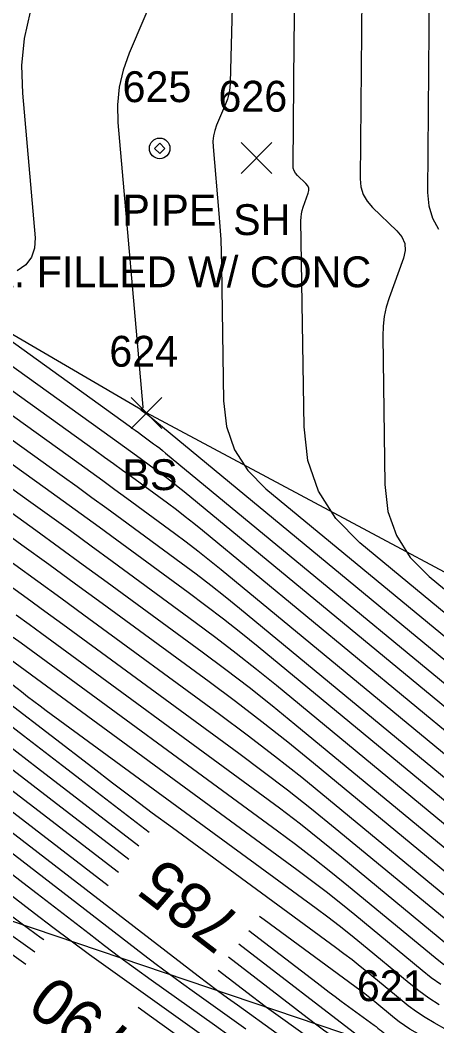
# Model space of a CAD drawing. Extents: x 1650836 to 1652450, y 332578 to 333908.
# Drawn here: x 1652265.5 to 1652292.5, y 332737.3 to 332802.5 of the extents above; entities that cross this region are included whole.
import ezdxf

# ---------------------------------------------------------------- set-up
doc = ezdxf.new("R2010")
doc.units = 0
for name, color, linetype in [('L_A', 7, 'Continuous'), ('L_I', 7, 'Continuous'), ('L_TIC', 7, 'Continuous'), ('LAWA', 7, 'Continuous'), ('LELB', 7, 'Continuous'), ('LSOGCMA', 7, 'Continuous'), ('LSOGCMA_T', 7, 'Continuous'), ('LSOGCMI', 7, 'Continuous'), ('M_A', 7, 'Continuous'), ('M_C', 7, 'Continuous'), ('M_I', 7, 'Continuous'), ('MPIP', 7, 'Continuous')]:
    doc.layers.add(name, color=color, linetype=linetype)

msp = doc.modelspace()

# ---------------------------------------------------------------- linework, layer by layer
at = {"layer": 'L_TIC'}
for points in [[(1652279.805, 332792.553), (1652281.805, 332794.553)], [(1652281.805, 332792.553), (1652279.805, 332794.553)], [(1652272.674, 332776.021), (1652274.674, 332778.021)], [(1652274.674, 332776.021), (1652272.674, 332778.021)]]:
    msp.add_lwpolyline(points, dxfattribs=at)
at = {"layer": 'LAWA'}
msp.add_lwpolyline([(1652408.76, 332665.713), (1652363.38, 332695.402), (1652324.46, 332714.991), (1652289.155, 332735.895), (1652253.497, 332747.946), (1652218.614, 332766.122), (1652198.198, 332775.017), (1652146.456, 332804.843), (1652136.841, 332807.592), (1652091.374, 332831.511), (1652057.601, 332848.138), (1652027.653, 332867.625)], dxfattribs=at)
at = {"layer": 'LELB'}
msp.add_lwpolyline([(1652415.318, 332676.268), (1652374.578, 332707.318), (1652335.114, 332741.334), (1652308.938, 332758.195), (1652273.674, 332777.021), (1652240.738, 332796.253), (1652212.676, 332810.498), (1652191.609, 332828.678)], dxfattribs=at)
at = {"layer": 'LSOGCMA'}
for points in [[(1652279.538, 332814.747), (1652279.104, 332798.44), (1652279.078, 332798.076), (1652279.017, 332797.72), (1652278.924, 332797.371), (1652278.797, 332797.029), (1652278.221, 332795.677), (1652278.099, 332795.336), (1652278.021, 332794.987), (1652277.987, 332794.632), (1652277.997, 332794.269), (1652278.375, 332789.946), (1652278.441, 332789.103), (1652278.492, 332788.26), (1652278.527, 332787.415), (1652278.547, 332786.57), (1652278.678, 332777.807), (1652278.868, 332776.144), (1652279.388, 332774.639), (1652280.238, 332773.293), (1652281.417, 332772.104), (1652304.103, 332753.383)], [(1652207.289, 332796.117), (1652228.455, 332780.692), (1652228.555, 332780.619), (1652228.655, 332780.547), (1652228.756, 332780.475), (1652228.857, 332780.404), (1652229.261, 332780.119), (1652229.361, 332780.048), (1652229.462, 332779.976), (1652229.561, 332779.902), (1652229.66, 332779.829), (1652231.418, 332778.505), (1652231.744, 332778.261), (1652232.072, 332778.017), (1652232.4, 332777.776), (1652232.73, 332777.535), (1652253.597, 332762.371), (1652257.064, 332759.833), (1652260.514, 332757.272), (1652263.946, 332754.687), (1652267.36, 332752.078), (1652272.52, 332748.107)], [(1652294.692, 332745.911), (1652284.503, 332754.319), (1652282.838, 332755.673), (1652281.154, 332757.003), (1652279.451, 332758.309), (1652277.729, 332759.59), (1652270.803, 332764.666), (1652269.071, 332765.934), (1652267.335, 332767.196), (1652265.596, 332768.455), (1652263.854, 332769.709), (1652256.417, 332775.051), (1652254.6, 332776.364), (1652252.791, 332777.687), (1652250.989, 332779.02), (1652249.194, 332780.363), (1652240.495, 332786.912), (1652238.442, 332788.444), (1652236.378, 332789.961), (1652234.301, 332791.461), (1652232.213, 332792.944), (1652229.96, 332794.531)], [(1652279.653, 332742.619), (1652287.635, 332736.477), (1652287.714, 332736.417), (1652287.794, 332736.357), (1652287.874, 332736.298), (1652287.955, 332736.24), (1652288.279, 332736.009), (1652288.359, 332735.951), (1652288.439, 332735.892), (1652288.518, 332735.831), (1652288.597, 332735.77), (1652289.157, 332735.326), (1652289.277, 332735.232), (1652289.396, 332735.137), (1652289.515, 332735.042), (1652289.634, 332734.946), (1652309.319, 332719.049)]]:
    msp.add_lwpolyline(points, dxfattribs=at)
at = {"layer": 'LSOGCMI'}
for points in [[(1652287.7, 332811.246), (1652287.539, 332792.197), (1652287.585, 332791.671), (1652287.731, 332791.187), (1652287.978, 332790.746), (1652288.325, 332790.347), (1652289.914, 332788.839), (1652290.238, 332788.444), (1652290.417, 332788.016), (1652290.449, 332787.552), (1652290.336, 332787.054), (1652289.408, 332784.485), (1652289.219, 332783.881), (1652289.087, 332783.267), (1652289.012, 332782.643), (1652288.993, 332782.01), (1652289.136, 332772.375), (1652289.335, 332770.639), (1652289.878, 332769.068), (1652290.765, 332767.663), (1652291.996, 332766.423), (1652305.777, 332755.05)], [(1652292.795, 332809.573), (1652292.229, 332808.51), (1652292.032, 332807.144), (1652291.899, 332791.32), (1652291.974, 332790.452), (1652292.215, 332789.656), (1652292.621, 332788.929)], [(1652298.244, 332747.551), (1652280.907, 332761.858), (1652279.794, 332762.763), (1652278.67, 332763.651), (1652277.532, 332764.523), (1652276.382, 332765.379), (1652271.757, 332768.77), (1652270.599, 332769.616), (1652269.44, 332770.459), (1652268.279, 332771.3), (1652267.115, 332772.138), (1652249.162, 332785.034), (1652248.082, 332785.814), (1652247.007, 332786.6), (1652245.936, 332787.392), (1652244.869, 332788.191), (1652240.612, 332791.396), (1652239.544, 332792.193), (1652238.471, 332792.981), (1652237.391, 332793.761), (1652236.305, 332794.533), (1652216.969, 332808.155)], [(1652274.384, 332804.669), (1652272.543, 332800.346), (1652272.153, 332799.254), (1652271.904, 332798.14), (1652271.795, 332797.003), (1652271.827, 332795.844), (1652273.44, 332777.39), (1652273.439, 332777.368), (1652273.433, 332777.349), (1652273.42, 332777.333), (1652273.403, 332777.32), (1652273.319, 332777.275), (1652273.304, 332777.264), (1652273.298, 332777.252), (1652273.302, 332777.239), (1652273.316, 332777.225), (1652273.638, 332776.994), (1652273.663, 332776.976), (1652273.689, 332776.957), (1652273.702, 332776.947), (1652273.714, 332776.937), (1652303.266, 332752.55)], [(1652304.94, 332754.217), (1652287.508, 332768.602), (1652285.952, 332770.171), (1652284.83, 332771.948), (1652284.143, 332773.935), (1652283.891, 332776.131), (1652283.693, 332789.481), (1652283.7, 332789.705), (1652283.726, 332789.925), (1652283.773, 332790.141), (1652283.839, 332790.354), (1652284.167, 332791.261), (1652284.207, 332791.436), (1652284.195, 332791.6), (1652284.132, 332791.751), (1652284.018, 332791.89), (1652283.457, 332792.422), (1652283.335, 332792.563), (1652283.248, 332792.718), (1652283.196, 332792.889), (1652283.18, 332793.075), (1652283.248, 332801.062), (1652283.263, 332802.458), (1652283.284, 332803.853)], [(1652226.364, 332803.026), (1652237.669, 332795.062), (1652238.421, 332794.528), (1652239.168, 332793.988), (1652239.912, 332793.442), (1652240.651, 332792.89), (1652243.598, 332790.671), (1652244.337, 332790.119), (1652245.078, 332789.57), (1652245.823, 332789.026), (1652246.57, 332788.486), (1652268.202, 332772.947), (1652269.173, 332772.248), (1652270.142, 332771.547), (1652271.109, 332770.843), (1652272.075, 332770.137), (1652275.933, 332767.309), (1652276.893, 332766.595), (1652277.842, 332765.867), (1652278.78, 332765.126), (1652279.708, 332764.372), (1652299.081, 332748.385)], [(1652266.13, 332803.016), (1652265.746, 332801.298), (1652265.578, 332799.546), (1652265.627, 332797.759), (1652266.447, 332788.384), (1652266.422, 332787.706), (1652266.221, 332787.122), (1652265.844, 332786.634), (1652265.291, 332786.24)], [(1652301.592, 332750.884), (1652276.112, 332771.911), (1652275.737, 332772.216), (1652275.358, 332772.515), (1652274.974, 332772.809), (1652274.587, 332773.098), (1652273.028, 332774.24), (1652272.638, 332774.526), (1652272.247, 332774.81), (1652271.856, 332775.093), (1652271.463, 332775.376), (1652251.94, 332789.4), (1652251.079, 332790.217), (1652250.824, 332790.995), (1652251.176, 332791.734), (1652252.134, 332792.435), (1652257.93, 332795.565), (1652258.695, 332796.109), (1652259.216, 332796.785), (1652259.493, 332797.591), (1652259.527, 332798.529), (1652259.177, 332802.543)], [(1652273.843, 332749.826), (1652265.697, 332756.094), (1652263.77, 332757.566), (1652261.833, 332759.025), (1652259.886, 332760.471), (1652257.929, 332761.904), (1652250.031, 332767.643), (1652248.097, 332769.055), (1652246.169, 332770.475), (1652244.246, 332771.903), (1652242.33, 332773.339), (1652232.009, 332781.108), (1652231.428, 332781.542), (1652230.844, 332781.971), (1652230.256, 332782.396), (1652229.665, 332782.816), (1652227.293, 332784.487), (1652226.701, 332784.906), (1652226.11, 332785.327), (1652225.521, 332785.751), (1652224.934, 332786.177), (1652208.765, 332797.96)], [(1652208.027, 332797.039), (1652226.695, 332783.434), (1652227.038, 332783.185), (1652227.383, 332782.937), (1652227.728, 332782.691), (1652228.075, 332782.445), (1652229.463, 332781.468), (1652229.809, 332781.222), (1652230.153, 332780.973), (1652230.495, 332780.722), (1652230.835, 332780.468), (1652236.874, 332775.922), (1652237.995, 332775.082), (1652239.12, 332774.246), (1652240.249, 332773.415), (1652241.38, 332772.589), (1652255.679, 332762.198), (1652258.433, 332760.183), (1652261.173, 332758.148), (1652263.899, 332756.095), (1652266.611, 332754.023), (1652273.182, 332748.967)], [(1652296.047, 332747.84), (1652282.105, 332759.345), (1652280.809, 332760.4), (1652279.498, 332761.435), (1652278.172, 332762.452), (1652276.831, 332763.449), (1652271.439, 332767.402), (1652270.09, 332768.388), (1652268.738, 332769.372), (1652267.384, 332770.352), (1652266.028, 332771.328), (1652251.754, 332781.582), (1652250.342, 332782.602), (1652248.936, 332783.63), (1652247.535, 332784.666), (1652246.14, 332785.71), (1652240.573, 332789.901), (1652239.177, 332790.943), (1652237.773, 332791.974), (1652236.361, 332792.994), (1652234.941, 332794.003), (1652231.364, 332796.523)], [(1652295.369, 332746.876), (1652283.304, 332756.832), (1652281.823, 332758.036), (1652280.326, 332759.219), (1652278.811, 332760.38), (1652277.28, 332761.52), (1652271.121, 332766.034), (1652269.58, 332767.161), (1652268.036, 332768.284), (1652266.49, 332769.403), (1652264.941, 332770.519), (1652254.346, 332778.13), (1652252.601, 332779.39), (1652250.864, 332780.66), (1652249.134, 332781.94), (1652247.411, 332783.229), (1652240.534, 332788.406), (1652238.81, 332789.694), (1652237.075, 332790.967), (1652235.331, 332792.227), (1652233.577, 332793.474), (1652230.662, 332795.527)], [(1652300.755, 332750.051), (1652277.31, 332769.398), (1652276.751, 332769.853), (1652276.186, 332770.299), (1652275.614, 332770.738), (1652275.036, 332771.168), (1652272.71, 332772.873), (1652272.128, 332773.298), (1652271.545, 332773.722), (1652270.961, 332774.145), (1652270.376, 332774.566), (1652241.387, 332795.39)], [(1652229.258, 332793.535), (1652231.078, 332792.253), (1652233.386, 332790.613), (1652235.681, 332788.956), (1652237.963, 332787.28), (1652240.232, 332785.586), (1652251.766, 332776.903), (1652253.237, 332775.802), (1652254.714, 332774.71), (1652256.197, 332773.625), (1652257.686, 332772.549), (1652263.655, 332768.262), (1652265.146, 332767.188), (1652266.635, 332766.111), (1652268.12, 332765.03), (1652269.603, 332763.946), (1652278.411, 332757.49), (1652280.207, 332756.153), (1652281.984, 332754.79), (1652283.741, 332753.403), (1652285.479, 332751.99), (1652294.014, 332744.946)], [(1652228.557, 332792.539), (1652230.876, 332790.905), (1652232.939, 332789.439), (1652234.99, 332787.958), (1652237.03, 332786.46), (1652239.057, 332784.946), (1652254.338, 332773.443), (1652255.485, 332772.584), (1652256.637, 332771.732), (1652257.794, 332770.887), (1652258.956, 332770.047), (1652263.611, 332766.703), (1652264.774, 332765.866), (1652265.935, 332765.026), (1652267.093, 332764.183), (1652268.25, 332763.337), (1652279.664, 332754.97), (1652281.251, 332753.789), (1652282.821, 332752.586), (1652284.373, 332751.36), (1652285.908, 332750.112), (1652293.336, 332743.982)], [(1652243.979, 332791.938), (1652269.289, 332773.757), (1652270.067, 332773.197), (1652270.844, 332772.635), (1652271.619, 332772.071), (1652272.392, 332771.505), (1652275.484, 332769.238), (1652276.253, 332768.666), (1652277.014, 332768.083), (1652277.766, 332767.489), (1652278.509, 332766.885), (1652299.918, 332749.218)], [(1652262.628, 332783.312), (1652272.551, 332776.185), (1652272.75, 332776.041), (1652272.949, 332775.897), (1652273.147, 332775.753), (1652273.346, 332775.608), (1652274.138, 332775.027), (1652274.335, 332774.881), (1652274.53, 332774.731), (1652274.722, 332774.579), (1652274.913, 332774.424), (1652302.429, 332751.717)], [(1652265.235, 332763.941), (1652266.066, 332763.335), (1652266.897, 332762.728), (1652280.918, 332752.45), (1652282.295, 332751.425), (1652283.658, 332750.381), (1652285.005, 332749.317), (1652286.337, 332748.234), (1652293.221, 332742.552)], [(1652265.04, 332762.488), (1652265.544, 332762.12), (1652282.172, 332749.93), (1652283.339, 332749.062), (1652284.494, 332748.176), (1652285.636, 332747.274), (1652286.766, 332746.356), (1652292.384, 332741.719), (1652292.953, 332741.271)], [(1652292.76, 332739.972), (1652292.144, 332740.415), (1652291.547, 332740.886), (1652287.195, 332744.478), (1652286.268, 332745.231), (1652285.331, 332745.971), (1652284.384, 332746.698), (1652283.425, 332747.411), (1652264.19, 332761.511)], [(1652292.647, 332738.659), (1652291.982, 332739.094), (1652291.336, 332739.559), (1652290.71, 332740.053), (1652287.624, 332742.6), (1652286.9, 332743.189), (1652286.168, 332743.767), (1652285.428, 332744.334), (1652284.679, 332744.891), (1652267.18, 332757.719), (1652266.773, 332758.019), (1652266.367, 332758.322), (1652265.964, 332758.627), (1652265.562, 332758.934), (1652263.87, 332760.236)], [(1652294.867, 332736.065), (1652292.331, 332737.496), (1652291.755, 332737.839), (1652291.195, 332738.205), (1652290.652, 332738.596), (1652290.125, 332739.012), (1652288.053, 332740.722), (1652287.532, 332741.146), (1652287.005, 332741.562), (1652286.472, 332741.97), (1652285.933, 332742.371), (1652275.354, 332750.127), (1652274.053, 332751.085), (1652272.759, 332752.052), (1652271.47, 332753.026), (1652270.187, 332754.007), (1652264.784, 332758.165)], [(1652262.98, 332754.064), (1652266.078, 332751.696), (1652271.859, 332747.248)], [(1652264.797, 332751.314), (1652271.198, 332746.389)], [(1652280.12, 332737.068), (1652276.78, 332739.45), (1652275.948, 332740.05), (1652275.122, 332740.656), (1652274.301, 332741.271), (1652273.485, 332741.892), (1652262.234, 332750.55)], [(1652263.515, 332750.932), (1652277.023, 332740.539), (1652277.654, 332740.057), (1652278.29, 332739.582), (1652278.93, 332739.112), (1652279.574, 332738.648), (1652282.159, 332736.803)], [(1652279.098, 332736.596), (1652278.08, 332737.333), (1652273.987, 332740.253), (1652272.967, 332740.988), (1652271.954, 332741.731), (1652270.948, 332742.484), (1652269.948, 332743.246), (1652260.952, 332750.168)], [(1652259.671, 332749.786), (1652266.411, 332744.6), (1652267.594, 332743.698), (1652268.786, 332742.806), (1652269.986, 332741.925), (1652271.193, 332741.055), (1652276.04, 332737.597), (1652277.246, 332736.726)], [(1652260.434, 332745.16), (1652265.854, 332741.293)], [(1652267.008, 332742.859), (1652266.838, 332742.981), (1652265.616, 332743.878), (1652264.402, 332744.786)], [(1652292.644, 332735.999), (1652291.096, 332736.873), (1652290.743, 332737.083), (1652290.401, 332737.307), (1652290.069, 332737.546), (1652289.748, 332737.799), (1652288.482, 332738.844), (1652288.163, 332739.103), (1652287.841, 332739.357), (1652287.516, 332739.607), (1652287.187, 332739.852), (1652281.311, 332744.159), (1652281.009, 332744.381)], [(1652266.429, 332742.073), (1652264.251, 332743.627)], [(1652280.314, 332743.478), (1652284.738, 332740.075), (1652285.127, 332739.777), (1652285.519, 332739.481), (1652285.912, 332739.187), (1652286.307, 332738.896), (1652288.44, 332737.332), (1652288.56, 332737.243), (1652288.678, 332737.152), (1652288.795, 332737.06), (1652288.911, 332736.966), (1652289.37, 332736.587), (1652289.487, 332736.495), (1652289.608, 332736.408), (1652289.732, 332736.326), (1652289.86, 332736.251), (1652290.422, 332735.933), (1652290.556, 332735.852), (1652290.683, 332735.761), (1652290.804, 332735.663), (1652290.918, 332735.555), (1652292.142, 332734.326), (1652292.386, 332734.087), (1652292.636, 332733.855)], [(1652278.992, 332741.76), (1652284.097, 332737.831), (1652284.361, 332737.63), (1652284.626, 332737.432), (1652284.892, 332737.236), (1652285.161, 332737.043), (1652286.239, 332736.274), (1652286.507, 332736.08), (1652286.773, 332735.883), (1652287.036, 332735.682), (1652287.297, 332735.479), (1652289.163, 332734.003), (1652289.56, 332733.688), (1652289.956, 332733.372), (1652290.351, 332733.055), (1652290.746, 332732.737), (1652307.879, 332718.902)], [(1652278.331, 332740.9), (1652280.56, 332739.185), (1652281.007, 332738.844), (1652281.458, 332738.507), (1652281.911, 332738.174), (1652282.367, 332737.845), (1652284.199, 332736.539), (1652284.655, 332736.209), (1652285.106, 332735.874), (1652285.554, 332735.533), (1652285.997, 332735.187), (1652289.168, 332732.679), (1652289.842, 332732.144), (1652290.516, 332731.607), (1652291.188, 332731.069), (1652291.859, 332730.528), (1652306.919, 332718.366), (1652309.668, 332716.179), (1652312.447, 332714.032), (1652315.257, 332711.926), (1652318.098, 332709.859), (1652342.937, 332692.063)], [(1652293.318, 332722.786), (1652291.845, 332723.961), (1652290.368, 332725.132), (1652279.498, 332733.73), (1652278.143, 332734.789), (1652276.775, 332735.83), (1652275.394, 332736.855), (1652274, 332737.862), (1652273.139, 332738.477)]]:
    msp.add_lwpolyline(points, dxfattribs=at)
at = {"layer": 'MPIP'}
msp.add_lwpolyline([(1652274.864, 332794.172), (1652274.531, 332794.506), (1652274.197, 332794.172), (1652274.531, 332793.839)], close=True, dxfattribs=at)
msp.add_circle((1652274.531, 332794.172), 0.667, dxfattribs=at)

# ---------------------------------------------------------------- texts
at = {"layer": 'L_A'}
for s, p in [('SH', (1652279.293, 332788.553)), ('BS', (1652272.115, 332772.021))]:
    msp.add_text(s, height=2, dxfattribs=at).set_placement(p)
at = {"layer": 'L_I'}
for s, p in [('626', (1652278.34, 332796.553)), ('624', (1652271.265, 332780.021)), ('621', (1652287.313, 332738.895))]:
    msp.add_text(s, height=2, dxfattribs=at).set_placement(p)
at = {"layer": 'LSOGCMA_T'}
for s, rotation, p in [('785', 142.42277, (1652280.034, 332744.218)), ('790', 143.61902, (1652272.991, 332736.723))]:
    msp.add_text(s, height=3, rotation=rotation, dxfattribs=at).set_placement(p)
at = {"layer": 'M_A'}
msp.add_text('IPIPE', height=2, dxfattribs=at).set_placement((1652271.366, 332789.172))
at = {"layer": 'M_C'}
msp.add_text('2 IN DIA. FILLED W/ CONC', height=2, dxfattribs=at).set_placement((1652254.964, 332785.172))
at = {"layer": 'M_I'}
msp.add_text('625', height=2, dxfattribs=at).set_placement((1652272.121, 332797.172))

doc.saveas('drawing.dxf')
